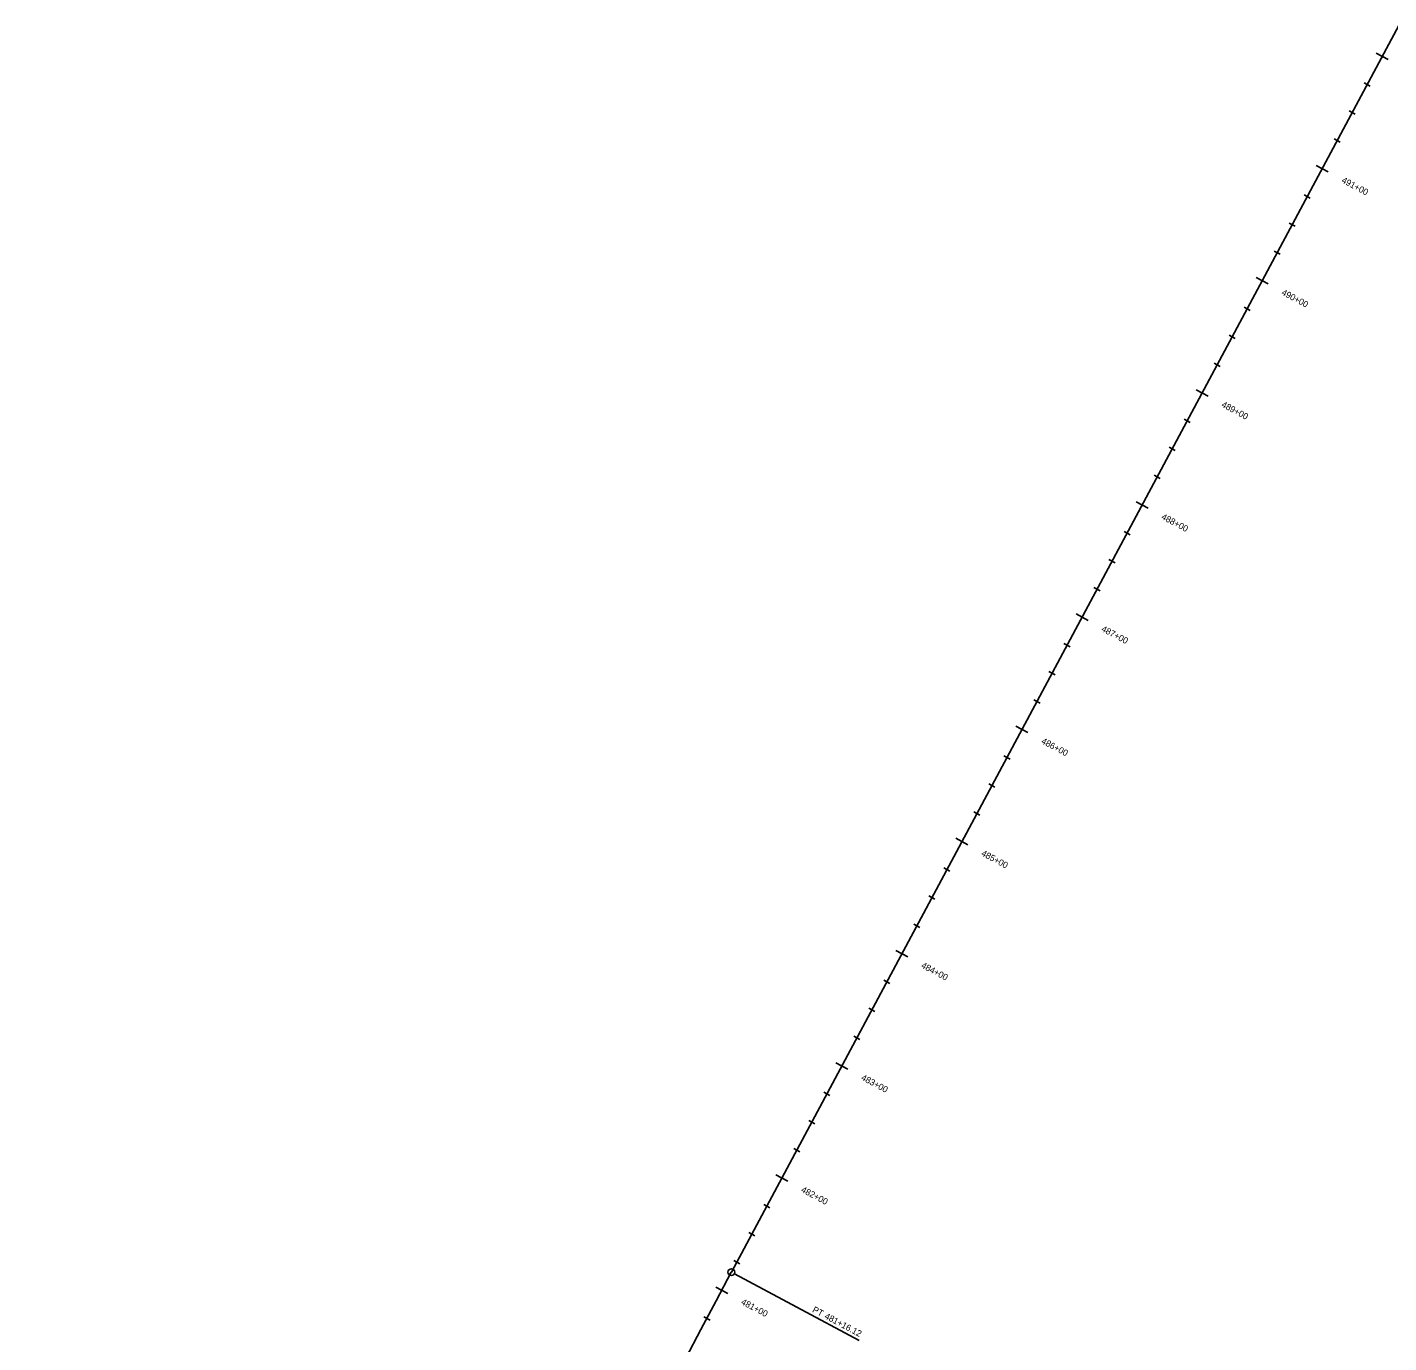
# Model space of a CAD drawing. Extents: x 2300830 to 2307917, y 756066 to 766359.
# Drawn here: x 2300916 to 2301986, y 757561 to 758595 of the extents above; entities that cross this region are included whole.
import ezdxf

# ---------------------------------------------------------------- set-up
doc = ezdxf.new("R2010")
doc.units = 0
for name, color, linetype in [('Default', 7, 'Continuous'), ('Draft_Station Cardinal Lines', 7, 'Continuous'), ('Draft_Station Cardinal Points', 7, 'Continuous'), ('Draft_Station Labels Major', 7, 'Continuous'), ('Draft_Station Ticks Major', 7, 'Continuous'), ('Draft_Station Ticks Minor', 7, 'Continuous'), ('Geom_Baseline', 7, 'Continuous')]:
    doc.layers.add(name, color=color, linetype=linetype)

msp = doc.modelspace()

# ---------------------------------------------------------------- linework, layer by layer
at = {"layer": 'Default'}
msp.add_line((2301469, 757616.6), (2303797.1, 761965), dxfattribs=at)
msp.add_line((2301469, 757616.6), (2303797.1, 761965), dxfattribs=at)
at = {"layer": 'Draft_Station Cardinal Lines'}
msp.add_line((2301471.4, 757615.4), (2301569.5, 757562.8), dxfattribs=at)
at = {"layer": 'Draft_Station Cardinal Points'}
for p, q in [((2301469, 757616.6), (2301469, 757616.6)), ((2301569.5, 757562.8), (2301569.5, 757562.8))]:
    msp.add_line(p, q, dxfattribs=at)
msp.add_circle((2301469, 757616.6), 2.67, dxfattribs=at)
at = {"layer": 'Draft_Station Ticks Major'}
for p, q in [((2301975.9, 758574.7), (2301985.3, 758569.7)), ((2301928.7, 758486.5), (2301938.1, 758481.5)), ((2301881.5, 758398.4), (2301890.9, 758393.4)), ((2301834.3, 758310.2), (2301843.7, 758305.2)), ((2301787.1, 758222), (2301796.5, 758217)), ((2301739.9, 758133.9), (2301749.3, 758128.9)), ((2301692.7, 758045.7), (2301702.1, 758040.7)), ((2301645.5, 757957.6), (2301654.9, 757952.6)), ((2301598.3, 757869.4), (2301607.7, 757864.4)), ((2301551.1, 757781.2), (2301560.5, 757776.2)), ((2301503.9, 757693.1), (2301513.3, 757688.1)), ((2301456.7, 757604.9), (2301466.1, 757599.9))]:
    msp.add_line(p, q, dxfattribs=at)
at = {"layer": 'Draft_Station Ticks Minor'}
for p, q in [((2301966.4, 758551.4), (2301971.2, 758548.8)), ((2301954.6, 758529.4), (2301959.4, 758526.8)), ((2301942.8, 758507.3), (2301947.6, 758504.7)), ((2301919.2, 758463.3), (2301924, 758460.7)), ((2301907.4, 758441.2), (2301912.2, 758438.6)), ((2301895.6, 758419.2), (2301900.4, 758416.6)), ((2301872, 758375.1), (2301876.8, 758372.5)), ((2301860.2, 758353.1), (2301865, 758350.5)), ((2301848.4, 758331), (2301853.2, 758328.4)), ((2301824.8, 758286.9), (2301829.6, 758284.3)), ((2301813, 758264.9), (2301817.8, 758262.3)), ((2301801.2, 758242.9), (2301806, 758240.3)), ((2301777.6, 758198.8), (2301782.4, 758196.2)), ((2301765.8, 758176.7), (2301770.6, 758174.1)), ((2301754, 758154.7), (2301758.8, 758152.1)), ((2301730.4, 758110.6), (2301735.2, 758108)), ((2301718.6, 758088.6), (2301723.4, 758086)), ((2301706.8, 758066.5), (2301711.6, 758063.9)), ((2301683.2, 758022.5), (2301688, 758019.9)), ((2301671.4, 758000.4), (2301676.2, 757997.8)), ((2301659.6, 757978.4), (2301664.4, 757975.8)), ((2301636, 757934.3), (2301640.8, 757931.7)), ((2301624.2, 757912.3), (2301629, 757909.7)), ((2301612.4, 757890.2), (2301617.2, 757887.6)), ((2301588.8, 757846.1), (2301593.6, 757843.5)), ((2301577, 757824.1), (2301581.8, 757821.5)), ((2301565.2, 757802.1), (2301570, 757799.5)), ((2301541.6, 757758), (2301546.4, 757755.4)), ((2301529.8, 757735.9), (2301534.6, 757733.3)), ((2301518, 757713.9), (2301522.8, 757711.3)), ((2301494.4, 757669.8), (2301499.2, 757667.2)), ((2301482.6, 757647.8), (2301487.4, 757645.2)), ((2301470.8, 757625.7), (2301475.6, 757623.1)), ((2301447.3, 757581.6), (2301452.2, 757579))]:
    msp.add_line(p, q, dxfattribs=at)
at = {"layer": 'Geom_Baseline'}
msp.add_line((2301469, 757616.6), (2303797.1, 761965), dxfattribs=at)
msp.add_arc((2306463, 754942.8), 5664.8, 151.8357, 168.3229, dxfattribs=at)

# ---------------------------------------------------------------- texts
at = {"layer": 'Draft_Station Cardinal Points'}
for s, p in [('PT', (2301532.2, 757585.6)), ('481+16.12', (2301541.7, 757580.5))]:
    msp.add_text(s, height=5, rotation=331.8357, dxfattribs=at).set_placement(p)
at = {"layer": 'Draft_Station Labels Major'}
for s, rotation, p in [('491+00', 331.8357, (2301948.1, 758473.3)), ('490+00', 331.8357, (2301900.9, 758385.1)), ('489+00', 331.8357, (2301853.7, 758297)), ('488+00', 331.8357, (2301806.5, 758208.8)), ('487+00', 331.8357, (2301759.3, 758120.7)), ('486+00', 331.8357, (2301712.1, 758032.5)), ('485+00', 331.8357, (2301664.9, 757944.3)), ('484+00', 331.8357, (2301617.7, 757856.2)), ('483+00', 331.8357, (2301570.5, 757768)), ('482+00', 331.8357, (2301523.3, 757679.9)), ('481+00', 331.9987, (2301476.1, 757591.7))]:
    msp.add_text(s, height=5, rotation=rotation, dxfattribs=at).set_placement(p)

doc.saveas('drawing.dxf')
